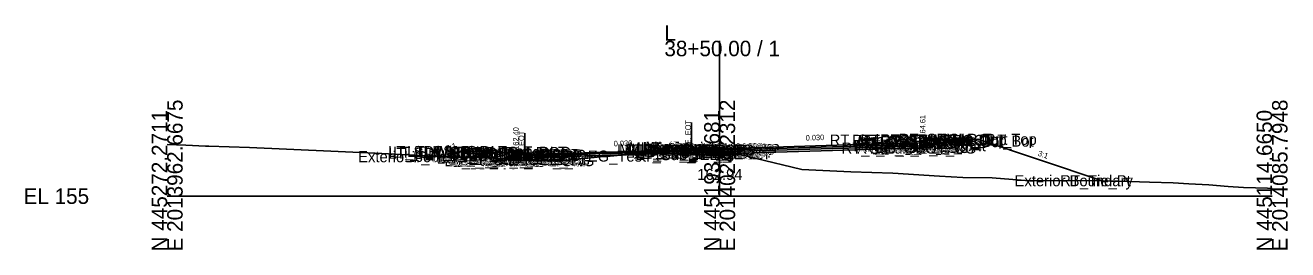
# Model space of a CAD drawing. Extents: x -26 to 4203, y -10 to 9526.
# Drawn here: x 1974.3 to 2202.8, y 8490.3 to 8530.9 of the extents above; entities that cross this region are included whole.
import ezdxf

# ---------------------------------------------------------------- set-up
doc = ezdxf.new("R2010")
doc.units = 0
for name, color, linetype in [('Default', 7, 'Continuous'), ('Exist CMT Pavement', 7, 'Continuous'), ('Exist Cross Section Cell', 7, 'Continuous'), ('Exist XS Center Line Elevation Label', 7, 'Continuous'), ('Exist XS Ground Line', 7, 'Continuous'), ('Prop CMT Conc Surface', 7, 'Continuous'), ('Prop CMT Concrete Structures', 7, 'Continuous'), ('Prop CMT Pvmt Course 1', 7, 'Continuous'), ('Prop CMT Pvmt Course 1 CG', 7, 'Continuous'), ('Prop CMT Pvmt Course 1 Wedge', 7, 'Continuous'), ('Prop CMT Pvmt Course 2', 7, 'Continuous'), ('Prop CMT Pvmt Course 2 Wedge', 7, 'Continuous'), ('Prop CMT Pvmt Course 3', 7, 'Continuous'), ('Prop CMT Pvmt Course 3 Wedge', 7, 'Continuous'), ('Prop CMT Pvmt Surface', 7, 'Continuous'), ('Prop CMT Pvmt Wedge Surface 1', 7, 'Continuous'), ('Prop CMT Pvmt Wedge Surface 2', 7, 'Continuous'), ('Prop CMT Pvmt Wedge Surface 3', 7, 'Continuous'), ('Prop CMT Slope Grass', 7, 'Continuous'), ('Prop CMT Subgrade Earthwork', 7, 'Continuous'), ('Prop XS Hydro Elevations', 7, 'Continuous'), ('Prop XS Label Text', 7, 'Continuous'), ('Prop XS SE Text', 7, 'Continuous'), ('Prop XS Side Slope Text', 7, 'Continuous'), ('Scratch_Level_0', 7, 'Continuous')]:
    doc.layers.add(name, color=color, linetype=linetype)

msp = doc.modelspace()

# ---------------------------------------------------------------- linework, layer by layer
at = {"layer": 'Exist CMT Pavement'}
for p, q in [((2092.29, 8508.19), (2093.66, 8508.29)), ((2093.66, 8508.29), (2094.88, 8508.36)), ((2067.25, 8506.43), (2068.19, 8506.42)), ((2068.19, 8506.42), (2071.18, 8506.42)), ((2071.18, 8506.42), (2072.66, 8506.57)), ((2072.66, 8506.57), (2074.76, 8506.77)), ((2074.76, 8506.77), (2076.13, 8506.91)), ((2076.13, 8506.91), (2078.99, 8507.16)), ((2078.99, 8507.16), (2082.95, 8507.5)), ((2082.95, 8507.5), (2085.29, 8507.68)), ((2085.29, 8507.68), (2088.44, 8507.94)), ((2088.44, 8507.94), (2092.29, 8508.19))]:
    msp.add_line(p, q, dxfattribs=at)
at = {"layer": 'Exist Cross Section Cell'}
for p, q in [((2100, 8500), (2100, 8528.13)), ((2000, 8500), (2100, 8500)), ((2100, 8500), (2200, 8500))]:
    msp.add_line(p, q, dxfattribs=at)
at = {"layer": 'Exist XS Ground Line'}
msp.add_lwpolyline([(2000, 8509.38), (2003.39, 8509.23), (2006.93, 8509.07), (2007.52, 8509.05), (2014.91, 8508.82), (2037.64, 8507.76), (2053.25, 8507.02), (2058.27, 8506.96), (2061.45, 8506.7), (2064.72, 8506.43), (2065.63, 8506.43), (2066.08, 8506.44), (2068.19, 8506.42), (2071.18, 8506.42), (2071.53, 8506.46), (2072.01, 8506.51), (2072.35, 8506.54), (2072.66, 8506.57), (2074.76, 8506.77), (2075.83, 8506.88), (2076.13, 8506.91), (2078.99, 8507.16), (2080.17, 8507.27), (2082.14, 8507.44), (2082.95, 8507.5), (2084.82, 8507.65), (2085.29, 8507.68), (2088.44, 8507.94), (2089.1, 8507.98), (2091.6, 8508.14), (2092.29, 8508.19), (2093.66, 8508.29), (2094.12, 8508.32), (2094.89, 8508.36), (2099.66, 8507.97), (2100, 8507.94), (2103.31, 8507.68), (2106.39, 8506.9), (2114.91, 8504.84), (2123.77, 8504.39), (2131.34, 8504.16), (2139.83, 8503.63), (2144.03, 8503.37), (2149.32, 8503.3), (2156.08, 8502.8), (2156.72, 8502.77), (2163.57, 8502.84), (2169.41, 8502.8), (2170.69, 8502.74), (2172.32, 8502.71), (2177.82, 8502.52), (2182.1, 8502.41), (2184.94, 8502.22), (2188.57, 8502.03), (2192.07, 8501.77), (2194.8, 8501.6), (2199.19, 8501.43), (2200, 8501.38)], dxfattribs=at)
at = {"layer": 'Prop CMT Conc Surface'}
for points in [[(2134.75, 8509.63), (2136.75, 8509.61)], [(2136.75, 8509.61), (2136.75, 8510.11), (2137.25, 8510.11)], [(2141.25, 8510.2), (2146.25, 8510.3)], [(2058.75, 8508), (2053.75, 8508.09)], [(2063.25, 8507.4), (2063.25, 8507.9), (2062.75, 8507.9)], [(2065.25, 8507.54), (2063.25, 8507.4)]]:
    msp.add_lwpolyline(points, dxfattribs=at)
at = {"layer": 'Prop CMT Concrete Structures'}
for points in [[(2091.5, 8508.33), (2091.51, 8508.5), (2092.26, 8508.75), (2093, 8508.82), (2093.74, 8508.84), (2094.49, 8508.59), (2094.5, 8508.42)], [(2094.5, 8508.42), (2091.5, 8508.33)], [(2134.75, 8509.63), (2136.75, 8509.61), (2136.75, 8510.11), (2137.25, 8510.11)], [(2137.25, 8510.11), (2137.25, 8509.12), (2134.75, 8509.05)], [(2134.75, 8509.05), (2134.75, 8509.63)], [(2146.25, 8510.3), (2141.25, 8510.2)], [(2141.25, 8510.2), (2141.25, 8509.87)], [(2141.25, 8509.87), (2146.25, 8509.97)], [(2146.25, 8509.97), (2146.25, 8510.3)], [(2053.75, 8507.76), (2053.75, 8508.09)], [(2053.75, 8508.09), (2058.75, 8508)], [(2058.75, 8507.66), (2053.75, 8507.76)], [(2058.75, 8508), (2058.75, 8507.66)], [(2065.25, 8507.54), (2063.25, 8507.4), (2063.25, 8507.9), (2062.75, 8507.9)], [(2062.75, 8507.9), (2062.75, 8506.89), (2065.25, 8506.96)], [(2065.25, 8506.96), (2065.25, 8507.54)]]:
    msp.add_lwpolyline(points, dxfattribs=at)
at = {"layer": 'Prop CMT Pvmt Course 1'}
for points in [[(2100, 8508.59), (2065.25, 8507.54)], [(2065.25, 8507.42), (2094.89, 8508.31)], [(2094.89, 8508.18), (2100, 8508.34)], [(2094.89, 8508.31), (2094.89, 8508.18)], [(2100, 8508.59), (2134.75, 8509.63)], [(2134.75, 8509.38), (2100, 8508.34)], [(2100, 8508.34), (2100, 8508.59)], [(2100, 8508.34), (2100, 8508.59)], [(2134.75, 8509.63), (2134.75, 8509.38)], [(2065.25, 8507.54), (2065.25, 8507.29), (2065.25, 8507.29), (2065.25, 8507.42)]]:
    msp.add_lwpolyline(points, dxfattribs=at)
msp.add_lwpolyline([(2100, 8508.34), (2100, 8508.46), (2100, 8508.46), (2100, 8508.34)], close=True, dxfattribs=at)
at = {"layer": 'Prop CMT Pvmt Course 1 CG'}
for points in [[(2134.75, 8509.05), (2137.75, 8509.14), (2138.07, 8508.81)], [(2134.75, 8508.71), (2134.75, 8509.05)], [(2138.07, 8508.81), (2134.75, 8508.71)], [(2065.25, 8506.96), (2062.25, 8506.87), (2061.82, 8506.44)], [(2061.82, 8506.44), (2067.25, 8506.61)], [(2065.25, 8506.54), (2065.25, 8506.96)]]:
    msp.add_lwpolyline(points, dxfattribs=at)
at = {"layer": 'Prop CMT Pvmt Course 1 Wedge'}
for points in [[(2065.25, 8507.42), (2065.39, 8507.42), (2065.63, 8507.43), (2066.08, 8507.44), (2068.19, 8507.51), (2071.18, 8507.6), (2071.53, 8507.61), (2072.01, 8507.62), (2072.35, 8507.63), (2072.66, 8507.64), (2074.76, 8507.71), (2075.83, 8507.74), (2076.13, 8507.75), (2078.99, 8507.83), (2080.17, 8507.87), (2082.14, 8507.93), (2082.84, 8507.95), (2082.95, 8507.95), (2082.97, 8507.95), (2083.19, 8507.96), (2084.82, 8508.01), (2085.29, 8508.02), (2088.25, 8508.11), (2088.44, 8508.12), (2089.1, 8508.14), (2091.6, 8508.21), (2092.29, 8508.23), (2093.23, 8508.26)], [(2093.23, 8508.26), (2092.29, 8508.19), (2091.6, 8508.14), (2090, 8508.04), (2089.1, 8508.01), (2088.44, 8507.99), (2088.25, 8507.98), (2085.29, 8507.9), (2084.82, 8507.88), (2083.19, 8507.83), (2082.97, 8507.83), (2082.95, 8507.83), (2082.84, 8507.82), (2082.14, 8507.8), (2080.17, 8507.74), (2078.99, 8507.71), (2076.13, 8507.62), (2075.83, 8507.61), (2074.76, 8507.58), (2072.66, 8507.52), (2072.35, 8507.51), (2072.01, 8507.5), (2071.53, 8507.48), (2071.18, 8507.47), (2068.19, 8507.38), (2066.08, 8507.32), (2065.63, 8507.31), (2065.39, 8507.3), (2065.25, 8507.29)], [(2065.25, 8507.29), (2065.25, 8507.42)]]:
    msp.add_lwpolyline(points, dxfattribs=at)
at = {"layer": 'Prop CMT Pvmt Course 2'}
for points in [[(2100, 8508.34), (2094.89, 8508.18)], [(2100, 8508.34), (2134.75, 8509.38)], [(2134.75, 8509.05), (2100, 8508)], [(2100, 8508), (2100, 8508.34)], [(2100, 8508), (2100, 8508.34)], [(2134.75, 8509.38), (2134.75, 8509.05)], [(2065.25, 8506.96), (2065.25, 8506.96), (2065.25, 8507.29), (2065.25, 8507.29)], [(2065.25, 8507.29), (2065.25, 8506.96)], [(2094.89, 8508.18), (2094.89, 8507.85)], [(2094.89, 8507.85), (2100, 8508)]]:
    msp.add_lwpolyline(points, dxfattribs=at)
at = {"layer": 'Prop CMT Pvmt Course 2 Wedge'}
for points in [[(2065.25, 8507.29), (2065.39, 8507.3), (2065.63, 8507.31), (2066.08, 8507.32), (2068.19, 8507.38), (2071.18, 8507.47), (2071.53, 8507.48), (2072.01, 8507.5), (2072.35, 8507.51), (2072.66, 8507.52), (2074.76, 8507.58), (2075.83, 8507.61), (2076.13, 8507.62), (2078.99, 8507.71), (2080.17, 8507.74), (2082.14, 8507.8), (2082.84, 8507.82), (2082.95, 8507.83), (2082.97, 8507.83), (2083.19, 8507.83), (2084.82, 8507.88), (2085.29, 8507.9), (2088.25, 8507.98), (2088.44, 8507.99), (2089.1, 8508.01), (2090, 8508.04)], [(2090, 8508.04), (2089.1, 8507.98), (2088.44, 8507.94), (2088.25, 8507.92), (2085.29, 8507.68), (2084.82, 8507.65), (2083.19, 8507.52), (2082.97, 8507.5), (2082.95, 8507.5), (2082.84, 8507.49), (2082.78, 8507.49), (2082.14, 8507.47), (2080.17, 8507.41), (2078.99, 8507.37), (2076.13, 8507.29), (2075.83, 8507.28), (2074.76, 8507.25), (2072.66, 8507.18), (2072.35, 8507.17), (2072.01, 8507.16), (2071.53, 8507.15), (2071.18, 8507.14), (2068.19, 8507.05), (2066.08, 8506.99), (2065.63, 8506.97), (2065.39, 8506.97), (2065.25, 8506.96)], [(2065.25, 8506.96), (2065.25, 8507.29)]]:
    msp.add_lwpolyline(points, dxfattribs=at)
at = {"layer": 'Prop CMT Pvmt Course 3'}
for points in [[(2100, 8508), (2134.75, 8509.05)], [(2134.75, 8508.71), (2100, 8507.67)], [(2134.75, 8509.05), (2134.75, 8508.71)], [(2065.25, 8506.96), (2065.25, 8506.96), (2065.25, 8506.63), (2065.25, 8506.63)], [(2065.25, 8506.63), (2065.25, 8506.96)], [(2100, 8508), (2094.89, 8507.85)], [(2094.89, 8507.85), (2094.89, 8507.52)], [(2094.89, 8507.52), (2100, 8507.67)], [(2100, 8507.67), (2100, 8508)], [(2100, 8507.67), (2100, 8508)]]:
    msp.add_lwpolyline(points, dxfattribs=at)
at = {"layer": 'Prop CMT Pvmt Course 3 Wedge'}
for points in [[(2065.25, 8506.96), (2065.39, 8506.97), (2065.63, 8506.97), (2066.08, 8506.99), (2068.19, 8507.05), (2071.18, 8507.14), (2071.53, 8507.15), (2072.01, 8507.16), (2072.35, 8507.17), (2072.66, 8507.18), (2074.76, 8507.25), (2075.83, 8507.28), (2076.13, 8507.29), (2078.99, 8507.37), (2080.17, 8507.41), (2082.14, 8507.47), (2082.78, 8507.49)], [(2082.78, 8507.49), (2082.14, 8507.44), (2080.17, 8507.27), (2078.99, 8507.16), (2076.13, 8506.91), (2075.83, 8506.88), (2074.76, 8506.77), (2072.66, 8506.57), (2072.35, 8506.54), (2072.01, 8506.51), (2071.53, 8506.46), (2071.18, 8506.42), (2068.19, 8506.42), (2066.08, 8506.44), (2065.63, 8506.43), (2065.39, 8506.43), (2065.25, 8506.43)], [(2065.25, 8506.54), (2065.25, 8506.96)]]:
    msp.add_lwpolyline(points, dxfattribs=at)
at = {"layer": 'Prop CMT Pvmt Surface'}
for points in [[(2100, 8508.59), (2065.25, 8507.54)], [(2100, 8508.59), (2134.75, 8509.63)]]:
    msp.add_lwpolyline(points, dxfattribs=at)
at = {"layer": 'Prop CMT Pvmt Wedge Surface 1'}
for points in [[(2094.89, 8508.31), (2065.25, 8507.42)], [(2100, 8508.34), (2094.89, 8508.18)], [(2094.89, 8508.18), (2094.89, 8508.31)], [(2100, 8508.59), (2100, 8508.34)], [(2065.25, 8507.29), (2065.25, 8507.54)], [(2065.25, 8507.42), (2065.25, 8507.29), (2065.25, 8507.29)]]:
    msp.add_lwpolyline(points, dxfattribs=at)
at = {"layer": 'Prop CMT Pvmt Wedge Surface 2'}
for points in [[(2100, 8508.34), (2065.25, 8507.29)], [(2100, 8508.59), (2100, 8508.34)], [(2065.25, 8507.29), (2065.25, 8507.54)]]:
    msp.add_lwpolyline(points, dxfattribs=at)
at = {"layer": 'Prop CMT Pvmt Wedge Surface 3'}
for points in [[(2100, 8508.59), (2100, 8508)], [(2100, 8508), (2065.25, 8506.96)], [(2065.25, 8506.96), (2065.25, 8507.54)]]:
    msp.add_lwpolyline(points, dxfattribs=at)
at = {"layer": 'Prop CMT Slope Grass'}
for points in [[(2137.25, 8510.11), (2146.75, 8510.3)], [(2146.75, 8510.3), (2169.25, 8502.8)], [(2053.25, 8508.09), (2050.43, 8507.15)], [(2062.75, 8507.9), (2053.25, 8508.09)]]:
    msp.add_lwpolyline(points, dxfattribs=at)
at = {"layer": 'Prop CMT Subgrade Earthwork'}
for points in [[(2100, 8507.67), (2094.89, 8507.52), (2094.88, 8508.36)], [(2100, 8507.67), (2134.75, 8508.71)], [(2134.75, 8508.71), (2138.07, 8508.81), (2139.41, 8510.15)], [(2067.25, 8506.61), (2061.82, 8506.44), (2060.31, 8507.95)], [(2067.25, 8506.61), (2067.25, 8506.43)]]:
    msp.add_lwpolyline(points, dxfattribs=at)
at = {"layer": 'Prop XS Label Text'}
for p, q in [((2094.89, 8513.36), (2094.89, 8508.36)), ((2064.72, 8511.43), (2064.72, 8506.43))]:
    msp.add_line(p, q, dxfattribs=at)

# ---------------------------------------------------------------- texts
at = {"layer": 'Default'}
msp.add_text('-', height=0.0001, dxfattribs=at).set_placement((2000, 8500))
at = {"layer": 'Exist Cross Section Cell'}
for s, p in [('L', (2090, 8528.13)), ('38+50.00 / 1', (2090, 8525.33)), ('EL 155', (1974, 8498.6))]:
    msp.add_text(s, height=2.8, dxfattribs=at).set_placement(p)
for s, p in [('N 445272.2711', (2000, 8490)), ('E 2013962.6675', (2002.8, 8490)), ('N 445193.4681', (2100, 8490)), ('E 2014024.2312', (2102.8, 8490)), ('N 445114.6650', (2200, 8490)), ('E 2014085.7948', (2202.8, 8490))]:
    msp.add_text(s, height=2.8, rotation=90, dxfattribs=at).set_placement(p)
at = {"layer": 'Exist XS Center Line Elevation Label'}
msp.add_text('162.94', height=2, dxfattribs=at).set_placement((2095.96, 8502.94))
at = {"layer": 'Prop XS Hydro Elevations'}
for s, p in [('164.61', (2137.25, 8510.61)), ('162.40', (2063.62, 8508.4))]:
    msp.add_text(s, height=1, rotation=90, dxfattribs=at).set_placement(p)
at = {"layer": 'Prop XS Label Text'}
for p in [(2094.79, 8509.39), (2064.62, 8507.46)]:
    msp.add_text('E. EOT', height=1, rotation=90, dxfattribs=at).set_placement(p)
at = {"layer": 'Prop XS SE Text'}
for rotation, p in [(1.7192, (2115.6, 8510.06)), (1.7176, (2080.85, 8509.01))]:
    msp.add_text('0.030', height=1, rotation=rotation, dxfattribs=at).set_placement(p)
at = {"layer": 'Prop XS Side Slope Text'}
for rotation, p in [(18.4349, (2050.69, 8508.17)), (341.5651, (2157.53, 8507.34))]:
    msp.add_text('3:1', height=1, rotation=rotation, dxfattribs=at).set_placement(p)
at = {"layer": 'Scratch_Level_0'}
for s, p in [('RT_Sub_Trench_Out_DLT', (2119.93, 8509.15)), ('RT_CG_Top_Face', (2123.96, 8509.11)), ('RT_CG_Top_Gut', (2124.94, 8508.61)), ('RT_PV1_OEOT', (2125.44, 8508.63)), ('RT_CG_Top_BOC', (2125.49, 8509.11)), ('RT_SDWK_In_Top', (2129.06, 8509.2)), ('RT_SDWK_In_Bot', (2129.09, 8508.87)), ('RT_SDWK_Out_Top', (2132.44, 8509.3)), ('RT_SDWK_Out_Bot', (2132.47, 8508.97)), ('CSLP_Pnt', (2139.62, 8509.3)), ('LT_SDWK_Out_Top', (2039.99, 8507.09)), ('LT_SDWK_Out_Bot', (2040.02, 8506.76)), ('LT_Sub_Trench_Out_DLT', (2040.88, 8506.95)), ('LT_CSLP_Pnt', (2043.42, 8507.09)), ('LT_SDWK_In_Top', (2046.61, 8507)), ('LT_SDWK_In_Bot', (2046.64, 8506.66)), ('LT_CG_Top_Face', (2050.51, 8506.9)), ('LT_CG_Top_BOC', (2051.03, 8506.9)), ('LT_CG_Top_Gut', (2051.49, 8506.4)), ('LT_PV2_OEEOP', (2054.56, 8506.29)), ('LT_PV1_OEEOP', (2055.12, 8506.42)), ('LT_PV2_OEOT', (2055.42, 8506.29)), ('LT_PV1_OEOT', (2055.99, 8506.54)), ('LT_PV_EG_TestPt', (2066.48, 8506.26)), ('LT_PV_Sub_Tie_In', (2081.44, 8507.36)), ('MI_Face Out', (2081.78, 8507.5)), ('MI_Bot Out', (2082.76, 8507.33)), ('LT_PV_IEEOP_EG', (2083.08, 8507.36)), ('MI_Top Out', (2083.49, 8507.75)), ('LT_Sub_IEEOP', (2084.75, 8506.52)), ('LT_PV2_IEEOP', (2084.84, 8507.18)), ('LT_PV3_IEEOP', (2084.84, 8506.85)), ('LT_PV1_IEEOP', (2085.41, 8507.31)), ('MI_Crown', (2086.07, 8507.82)), ('MI_Face In', (2086.38, 8507.59)), ('MI_Top In', (2086.59, 8507.84)), ('MI_Bot In', (2087.38, 8507.42)), ('RT_Sub_OEEOP', (2089.17, 8506.67)), ('RT_PV2_OEEOP', (2089.26, 8507.34)), ('RT_PV3_OEEOP', (2089.26, 8507)), ('RT_PV1_OEEOP', (2089.83, 8507.46)), ('RT_PV2_IEEOP', (2089.91, 8507.34)), ('RT_PV1_IEEOP', (2090.47, 8507.46)), ('LT_Sub_PGL', (2091.12, 8506.67)), ('RT_PV2_PGL', (2091.17, 8507.34)), ('LT_PV2_PGL', (2091.21, 8507.34)), ('LT_PV3_PGL', (2091.21, 8507)), ('RT_PV1_PGL', (2091.73, 8507.59)), ('LT_PV1_PGL', (2091.78, 8507.59)), ('RT_Sub_OEOT_CG', (2122.07, 8507.71)), ('RT_CG1_Shelf_Out', (2124.25, 8508.14)), ('RT_CG_Bot_IE', (2124.62, 8508.05)), ('RT_Sub_OEOT', (2124.78, 8507.71)), ('RT_PV2_OEOT', (2124.88, 8508.38)), ('RT_PV3_OEOT', (2124.88, 8508.05)), ('RT_CG_Bot_BOC', (2125.52, 8508.12)), ('RT_Sub_OEOP', (2128.14, 8507.81)), ('Exterior Boundary', (2034.57, 8506.15)), ('LT_Tie_Pt', (2042.87, 8506.15)), ('LT_CG1_Shelf_Out', (2048.8, 8505.87)), ('LT_PV_Sub_Tie_Out', (2050.21, 8505.43)), ('LT_CG_Bot_BOC', (2051.07, 8505.89)), ('LT_Sub_OEOP', (2051.93, 8505.44)), ('LT_Sub_OEOT_CG', (2052.62, 8505.54)), ('LT_PV_OEEOP_EG', (2052.79, 8505.43)), ('LT_Sub_OEEOP', (2054.46, 8505.63)), ('LT_PV3_OEEOP', (2054.56, 8505.96)), ('LT_CG_Bot_IE', (2055.16, 8505.96)), ('LT_Sub_OEOT', (2055.33, 8505.63)), ('LT_PV3_OEOT', (2055.42, 8505.96)), ('Exterior Boundary', (2153.39, 8501.8)), ('RT_Tie_Pt', (2161.64, 8501.8))]:
    msp.add_text(s, height=2, dxfattribs=at).set_placement(p)

doc.saveas('drawing.dxf')
